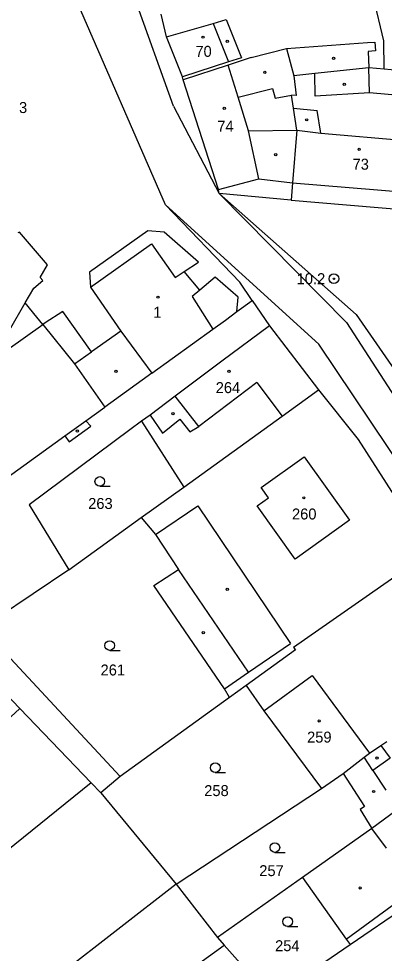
# Model space of a CAD drawing. Extents: x -762263 to -760336, y -1154405 to -1152076.
# Drawn here: x -761595.2 to -761538.5, y -1152630.1 to -1152485.2 of the extents above; entities that cross this region are included whole.
import ezdxf

# ---------------------------------------------------------------- set-up
doc = ezdxf.new("R2010")
doc.units = 0
for name, color, linetype in [('Vrstva 1', 7, 'Continuous'), ('Vrstva 17', 7, 'Continuous'), ('Vrstva 18', 7, 'Continuous'), ('Vrstva 19', 7, 'Continuous'), ('Vrstva 24', 7, 'Continuous'), ('Vrstva 25', 7, 'Continuous'), ('Vrstva 4', 7, 'Continuous'), ('Vrstva 6', 7, 'Continuous')]:
    doc.layers.add(name, color=color, linetype=linetype)

msp = doc.modelspace()

# ---------------------------------------------------------------- linework, layer by layer
at = {"layer": 'Vrstva 1'}
for p, q in [((-761571.15, -1152498.75), (-761590.9, -1152443.54)), ((-761538.58, -1152488.6), (-761541.49, -1152476.16)), ((-761572.43, -1152514.02), (-761586.48, -1152481.7)), ((-761572.23, -1152487.97), (-761573.06, -1152484.47)), ((-761569.78, -1152494.19), (-761572.23, -1152487.97)), ((-761538.53, -1152493.01), (-761538.58, -1152488.6)), ((-761559.12, -1152491.21), (-761553.64, -1152489.78)), ((-761553.64, -1152489.78), (-761552.51, -1152494.04)), ((-761562.68, -1152492.37), (-761569.68, -1152494.65)), ((-761559.12, -1152491.21), (-761562.68, -1152492.37)), ((-761549.28, -1152493.69), (-761552.51, -1152494.04)), ((-761540.89, -1152492.79), (-761549.28, -1152493.69)), ((-761538.53, -1152493.01), (-761540.89, -1152492.79)), ((-761535.28, -1152493.32), (-761538.53, -1152493.01)), ((-761569.68, -1152494.65), (-761569.78, -1152494.19)), ((-761564.22, -1152511.68), (-761569.68, -1152494.65)), ((-761552.51, -1152494.04), (-761552.14, -1152497.07)), ((-761552.14, -1152497.07), (-761552.9, -1152497.03)), ((-761552.59, -1152499.06), (-761552.9, -1152497.03)), ((-761571.15, -1152498.75), (-761564.07, -1152512.3)), ((-761552.06, -1152502.48), (-761552.59, -1152499.06)), ((-761552.06, -1152502.48), (-761552.74, -1152510.64)), ((-761552.74, -1152510.64), (-761552.93, -1152513.33)), ((-761564.07, -1152512.3), (-761564.22, -1152511.68)), ((-761564.07, -1152512.3), (-761542.83, -1152531.03)), ((-761552.93, -1152513.33), (-761564.07, -1152512.3)), ((-761560.88, -1152526.05), (-761572.43, -1152514.02)), ((-761552.93, -1152513.33), (-761533.03, -1152515)), ((-761595.05, -1152518.25), (-761595.28, -1152518.37)), ((-761590.69, -1152523.36), (-761595.05, -1152518.25)), ((-761575.15, -1152518.06), (-761584.18, -1152524.5)), ((-761572.62, -1152518.29), (-761575.15, -1152518.06)), ((-761567.27, -1152522.95), (-761572.62, -1152518.29)), ((-761591.82, -1152525.28), (-761590.69, -1152523.36)), ((-761569.52, -1152524.36), (-761567.27, -1152522.95)), ((-761591.42, -1152525.76), (-761591.82, -1152525.28)), ((-761584.18, -1152524.5), (-761584.02, -1152526.83)), ((-761567.08, -1152527.27), (-761569.52, -1152524.36)), ((-761564.73, -1152525.24), (-761567.08, -1152527.27)), ((-761561.15, -1152528.34), (-761564.73, -1152525.24)), ((-761594.15, -1152529.24), (-761592.81, -1152526.97)), ((-761592.81, -1152526.97), (-761591.42, -1152525.76)), ((-761584.02, -1152526.83), (-761579.33, -1152533.63)), ((-761558.96, -1152528.88), (-761560.88, -1152526.05)), ((-761561.33, -1152530.6), (-761561.15, -1152528.34)), ((-761596.59, -1152533.46), (-761594.15, -1152529.24)), ((-761592.38, -1152531.44), (-761594.15, -1152529.24)), ((-761561.33, -1152530.6), (-761558.96, -1152528.88)), ((-761558.96, -1152528.88), (-761556.3, -1152532.81)), ((-761591.45, -1152532.6), (-761592.38, -1152531.44)), ((-761588.33, -1152530.57), (-761591.08, -1152532.34)), ((-761583.89, -1152536.83), (-761588.33, -1152530.57)), ((-761563.13, -1152531.9), (-761561.33, -1152530.6)), ((-761542.83, -1152531.03), (-761524.57, -1152557.66)), ((-761591.08, -1152532.34), (-761591.45, -1152532.6)), ((-761565.09, -1152533.31), (-761563.13, -1152531.9)), ((-761556.3, -1152532.81), (-761563.66, -1152538.29)), ((-761556.3, -1152532.81), (-761548.69, -1152542.73)), ((-761579.33, -1152533.63), (-761583.89, -1152536.83)), ((-761579.33, -1152533.63), (-761574.54, -1152540.14)), ((-761574.54, -1152540.14), (-761565.09, -1152533.31)), ((-761563.66, -1152538.29), (-761570.92, -1152543.7)), ((-761574.54, -1152540.14), (-761580.88, -1152544.72)), ((-761554.34, -1152546.81), (-761548.69, -1152542.73)), ((-761548.69, -1152542.73), (-761542.55, -1152550.45)), ((-761570.92, -1152543.7), (-761574.79, -1152546.65)), ((-761584.74, -1152547.51), (-761581.82, -1152545.4)), ((-761580.88, -1152544.72), (-761581.82, -1152545.4)), ((-761574.79, -1152546.65), (-761576.12, -1152547.58)), ((-761569.59, -1152557.8), (-761554.34, -1152546.81)), ((-761587.34, -1152550.77), (-761584, -1152548.36)), ((-761584, -1152548.36), (-761584.74, -1152547.51)), ((-761576.12, -1152547.58), (-761577.96, -1152548.95)), ((-761576.12, -1152547.58), (-761569.59, -1152557.8)), ((-761596.82, -1152556.24), (-761588, -1152549.86)), ((-761577.96, -1152548.95), (-761593.54, -1152560.56)), ((-761588, -1152549.86), (-761587.34, -1152550.77)), ((-761542.55, -1152550.45), (-761531.37, -1152567.89)), ((-761576.16, -1152562.54), (-761569.59, -1152557.8)), ((-761593.54, -1152560.56), (-761587.4, -1152570.64)), ((-761587.4, -1152570.64), (-761576.16, -1152562.54)), ((-761576.16, -1152562.54), (-761573.95, -1152565.15)), ((-761573.95, -1152565.15), (-761570.4, -1152570.58)), ((-761531.37, -1152567.89), (-761552.58, -1152582.67)), ((-761587.4, -1152570.64), (-761600.84, -1152579.67)), ((-761574.2, -1152573.09), (-761570.4, -1152570.58)), ((-761563.29, -1152589.08), (-761574.2, -1152573.09)), ((-761600.84, -1152579.67), (-761579.44, -1152602.7)), ((-761552.27, -1152583.04), (-761559.92, -1152588.57)), ((-761552.58, -1152582.67), (-761552.27, -1152583.04)), ((-761562.51, -1152590.45), (-761563.29, -1152589.08)), ((-761559.92, -1152588.57), (-761562.51, -1152590.45)), ((-761559.92, -1152588.57), (-761557.19, -1152592.48)), ((-761562.51, -1152590.45), (-761579.44, -1152602.7)), ((-761557.19, -1152592.48), (-761548.23, -1152604.57)), ((-761540.78, -1152599.09), (-761539.02, -1152597.89)), ((-761539.02, -1152597.89), (-761538.11, -1152597.27)), ((-761541.59, -1152599.71), (-761540.78, -1152599.09)), ((-761544.89, -1152602.24), (-761541.59, -1152599.71)), ((-761548.23, -1152604.57), (-761544.89, -1152602.24)), ((-761544.89, -1152602.24), (-761541.57, -1152607.33)), ((-761579.44, -1152602.7), (-761582.45, -1152605.2)), ((-761582.45, -1152605.2), (-761570.74, -1152619.41)), ((-761570.74, -1152619.41), (-761548.23, -1152604.57)), ((-761543.8, -1152628.75), (-761512.5, -1152607.38)), ((-761541.57, -1152607.33), (-761542.24, -1152607.81)), ((-761542.24, -1152607.81), (-761540.45, -1152610.73)), ((-761535.75, -1152607.29), (-761540.45, -1152610.73)), ((-761540.45, -1152610.73), (-761551.17, -1152618.34)), ((-761551.17, -1152618.34), (-761564.33, -1152627.68)), ((-761551.17, -1152618.34), (-761544.39, -1152627.92)), ((-761570.74, -1152619.41), (-761564.33, -1152627.68)), ((-761564.33, -1152627.68), (-761563.31, -1152628.83)), ((-761544.39, -1152627.92), (-761543.8, -1152628.75)), ((-761563.31, -1152628.83), (-761555.97, -1152637.06)), ((-761555.97, -1152637.06), (-761543.8, -1152628.75))]:
    msp.add_line(p, q, dxfattribs=at)
at = {"layer": 'Vrstva 24'}
for radius in [0.75, 0.1]:
    msp.add_circle((-761546.31, -1152525.49), radius, dxfattribs=at)
at = {"layer": 'Vrstva 25'}
for p, q in [((-761582.59, -1152557.69), (-761580.99, -1152557.69)), ((-761581.06, -1152583.13), (-761579.46, -1152583.13)), ((-761564.7, -1152602.08), (-761563.1, -1152602.08)), ((-761555.46, -1152614.45), (-761553.86, -1152614.45)), ((-761553.48, -1152625.94), (-761551.88, -1152625.94))]:
    msp.add_line(p, q, dxfattribs=at)
for centre, radius in [((-761566.59, -1152488.04), 0.175), ((-761562.83, -1152488.68), 0.175), ((-761546.36, -1152491.3), 0.175), ((-761557.01, -1152493.5), 0.175), ((-761544.69, -1152495.36), 0.175), ((-761563.3, -1152499.08), 0.175), ((-761550.52, -1152500.85), 0.175), ((-761542.39, -1152505.44), 0.175), ((-761555.32, -1152506.25), 0.175), ((-761573.59, -1152528.36), 0.175), ((-761580.1, -1152539.85), 0.175), ((-761562.57, -1152539.86), 0.175), ((-761571.26, -1152546.43), 0.175), ((-761586.07, -1152549.12), 0.175), ((-761582.59, -1152556.94), 0.75), ((-761550.97, -1152559.47), 0.175), ((-761562.83, -1152573.65), 0.175), ((-761566.56, -1152580.39), 0.175), ((-761581.06, -1152582.38), 0.75), ((-761548.59, -1152594.08), 0.175), ((-761564.7, -1152601.33), 0.75), ((-761539.62, -1152599.82), 0.175), ((-761540.15, -1152605.01), 0.175), ((-761555.46, -1152613.7), 0.75), ((-761542.24, -1152619.96), 0.175), ((-761553.48, -1152625.19), 0.75)]:
    msp.add_circle(centre, radius, dxfattribs=at)
at = {"layer": 'Vrstva 4'}
for p, q in [((-761572.23, -1152487.97), (-761565, -1152485.9)), ((-761565, -1152485.9), (-761562.99, -1152485.32)), ((-761565, -1152485.9), (-761562.62, -1152491.88)), ((-761562.99, -1152485.32), (-761560.64, -1152491.24)), ((-761553.64, -1152489.78), (-761541.08, -1152488.88)), ((-761541.08, -1152488.88), (-761539.98, -1152488.8)), ((-761539.98, -1152488.8), (-761539.88, -1152490.18)), ((-761539.88, -1152490.18), (-761540.98, -1152490.25)), ((-761540.98, -1152490.25), (-761540.89, -1152492.79)), ((-761562.62, -1152491.88), (-761569.78, -1152494.19)), ((-761561.15, -1152497.33), (-761562.68, -1152492.37)), ((-761560.64, -1152491.24), (-761562.62, -1152491.88)), ((-761549.2, -1152497.18), (-761549.28, -1152493.69)), ((-761540.78, -1152496.69), (-761540.89, -1152492.79)), ((-761561.15, -1152497.33), (-761555.84, -1152495.98)), ((-761555.84, -1152495.98), (-761555.43, -1152497.47)), ((-761540.78, -1152496.69), (-761549.2, -1152497.18)), ((-761535.58, -1152497.15), (-761540.78, -1152496.69)), ((-761559.54, -1152502.55), (-761561.15, -1152497.33)), ((-761555.43, -1152497.47), (-761552.9, -1152497.03)), ((-761552.59, -1152499.06), (-761548.9, -1152499.39)), ((-761548.33, -1152502.91), (-761548.9, -1152499.39)), ((-761559.54, -1152502.55), (-761552.06, -1152502.48)), ((-761552.06, -1152502.48), (-761548.33, -1152502.91)), ((-761557.96, -1152509.99), (-761559.54, -1152502.55)), ((-761548.33, -1152502.91), (-761532.05, -1152504.31)), ((-761564.22, -1152511.68), (-761557.96, -1152509.99)), ((-761557.96, -1152509.99), (-761552.74, -1152510.64)), ((-761552.74, -1152510.64), (-761532.78, -1152512.26)), ((-761564.07, -1152512.3), (-761544.34, -1152532.27)), ((-761548.63, -1152535.63), (-761572.43, -1152514.02)), ((-761584.02, -1152526.83), (-761574.6, -1152520.1)), ((-761574.6, -1152520.1), (-761570.89, -1152525.29)), ((-761570.89, -1152525.29), (-761569.52, -1152524.36)), ((-761567.08, -1152527.27), (-761568.26, -1152528.26)), ((-761568.26, -1152528.26), (-761565.09, -1152533.31)), ((-761596.81, -1152536.41), (-761591.45, -1152532.6)), ((-761591.45, -1152532.6), (-761586.52, -1152538.69)), ((-761544.34, -1152532.27), (-761522.78, -1152565.81)), ((-761527.99, -1152566.5), (-761548.63, -1152535.63)), ((-761586.52, -1152538.69), (-761583.89, -1152536.83)), ((-761586.52, -1152538.69), (-761581.82, -1152545.4)), ((-761558.25, -1152541.58), (-761567.23, -1152548.43)), ((-761558.25, -1152541.58), (-761554.34, -1152546.81)), ((-761567.23, -1152548.43), (-761570.92, -1152543.7)), ((-761574.79, -1152546.65), (-761572.85, -1152549.42)), ((-761572.85, -1152549.42), (-761570.17, -1152547.26)), ((-761570.17, -1152547.26), (-761568.62, -1152549.25)), ((-761588, -1152549.86), (-761584.74, -1152547.51)), ((-761568.62, -1152549.25), (-761567.23, -1152548.43)), ((-761557.59, -1152557.86), (-761550.92, -1152553.09)), ((-761550.92, -1152553.09), (-761543.87, -1152562.96)), ((-761556.44, -1152559.47), (-761557.59, -1152557.86)), ((-761558.19, -1152560.72), (-761556.44, -1152559.47)), ((-761573.95, -1152565.15), (-761567.38, -1152560.69)), ((-761567.38, -1152560.69), (-761553.04, -1152582.07)), ((-761552.29, -1152568.98), (-761558.19, -1152560.72)), ((-761543.87, -1152562.96), (-761552.29, -1152568.98)), ((-761559.56, -1152586.53), (-761570.4, -1152570.58)), ((-761559.56, -1152586.53), (-761553.04, -1152582.07)), ((-761563.29, -1152589.08), (-761559.56, -1152586.53)), ((-761557.19, -1152592.48), (-761549.66, -1152587.03)), ((-761549.66, -1152587.03), (-761540.78, -1152599.09)), ((-761539.02, -1152597.89), (-761537.6, -1152599.85)), ((-761540.25, -1152601.75), (-761541.59, -1152599.71)), ((-761537.6, -1152599.85), (-761540.25, -1152601.75)), ((-761540.25, -1152601.75), (-761538.24, -1152604.81)), ((-761538.13, -1152613.79), (-761540.45, -1152610.73)), ((-761544.39, -1152627.92), (-761533.59, -1152619.96))]:
    msp.add_line(p, q, dxfattribs=at)
at = {"layer": 'Vrstva 6'}
for p, q in [((-761604.99, -1152581.83), (-761595.01, -1152592.12)), ((-761616.31, -1152611.88), (-761595.01, -1152592.12)), ((-761595.01, -1152592.12), (-761583.91, -1152603.67)), ((-761583.91, -1152603.67), (-761641.55, -1152650.06)), ((-761583.91, -1152603.67), (-761582.45, -1152605.2)), ((-761570.74, -1152619.41), (-761600.26, -1152642.23)), ((-761606.07, -1152659.78), (-761563.31, -1152628.83))]:
    msp.add_line(p, q, dxfattribs=at)

# ---------------------------------------------------------------- texts
at = {"layer": 'Vrstva 17'}
msp.add_text('10.2', height=1.7, dxfattribs=at).set_placement((-761552.077, -1152526.34))
at = {"layer": 'Vrstva 18'}
for s, p in [('3', (-761595.113, -1152499.8)), ('263', (-761584.393, -1152561.2)), ('261', (-761582.473, -1152587.02)), ('258', (-761566.403, -1152605.73)), ('257', (-761557.875, -1152618.14)), ('254', (-761555.423, -1152629.78))]:
    msp.add_text(s, height=1.7, dxfattribs=at).set_placement(p)
at = {"layer": 'Vrstva 19'}
for s, p in [('70', (-761567.773, -1152491.09)), ('74', (-761564.383, -1152502.7)), ('73', (-761543.413, -1152508.59)), ('1', (-761574.298, -1152531.54)), ('264', (-761564.623, -1152543.23)), ('260', (-761552.803, -1152562.83)), ('259', (-761550.463, -1152597.43))]:
    msp.add_text(s, height=1.7, dxfattribs=at).set_placement(p)

doc.saveas('drawing.dxf')
